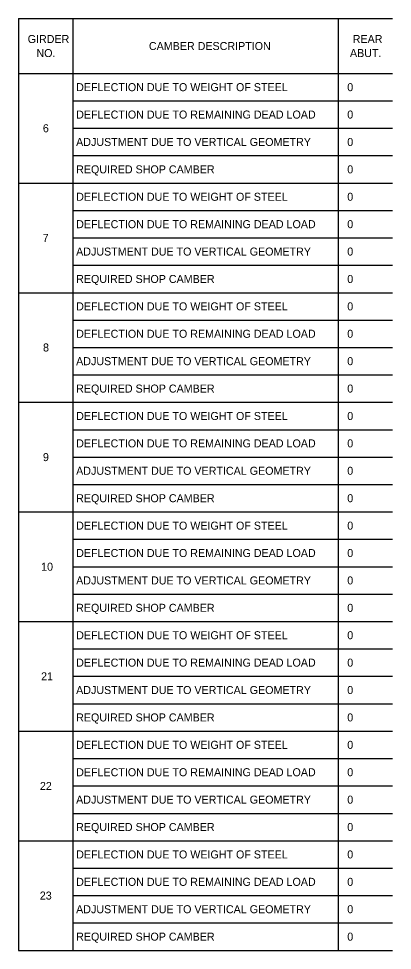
# Model space of a CAD drawing. Extents: x 3 to 33.4, y 1 to 20.5.
# Drawn here: x 3 to 10.19, y 2.58 to 20.5 of the extents above; entities that cross this region are included whole.
import ezdxf

# ---------------------------------------------------------------- set-up
doc = ezdxf.new("R2010")
doc.units = 0
doc.layers.add('BR_X_Beam_Object', color=7, linetype='Continuous')
doc.layers.add('BR_X_Slab_Object', color=7, linetype='Continuous')

msp = doc.modelspace()

# ---------------------------------------------------------------- linework, layer by layer
at = {"layer": 'BR_X_Slab_Object'}
for p, q in [((3, 20.5), (5.319, 20.5)), ((3, 20.5), (3, 2.58)), ((4.041, 20.5), (4.041, 2.58)), ((5.319, 20.5), (10.194, 20.5)), ((9.153, 20.5), (9.153, 2.58)), ((3, 19.446), (5.319, 19.446)), ((5.319, 19.446), (10.194, 19.446)), ((4.041, 18.919), (5.319, 18.919)), ((5.319, 18.919), (10.194, 18.919)), ((4.041, 18.392), (5.319, 18.392)), ((5.319, 18.392), (10.194, 18.392)), ((4.041, 17.865), (5.319, 17.865)), ((5.319, 17.865), (10.194, 17.865)), ((3, 17.338), (5.319, 17.338)), ((5.319, 17.338), (10.194, 17.338)), ((4.041, 16.811), (5.319, 16.811)), ((5.319, 16.811), (10.194, 16.811)), ((4.041, 16.284), (5.319, 16.284)), ((5.319, 16.284), (10.194, 16.284)), ((4.041, 15.756), (5.319, 15.756)), ((5.319, 15.756), (10.194, 15.756)), ((3, 15.229), (5.319, 15.229)), ((5.319, 15.229), (10.194, 15.229)), ((4.041, 14.702), (5.319, 14.702)), ((5.319, 14.702), (10.194, 14.702)), ((4.041, 14.175), (5.319, 14.175)), ((5.319, 14.175), (10.194, 14.175)), ((4.041, 13.648), (5.319, 13.648)), ((5.319, 13.648), (10.194, 13.648)), ((3, 13.121), (5.319, 13.121)), ((5.319, 13.121), (10.194, 13.121)), ((4.041, 12.594), (5.319, 12.594)), ((5.319, 12.594), (10.194, 12.594)), ((4.041, 12.067), (5.319, 12.067)), ((5.319, 12.067), (10.194, 12.067)), ((4.041, 11.54), (5.319, 11.54)), ((5.319, 11.54), (10.194, 11.54)), ((3, 11.013), (5.319, 11.013)), ((5.319, 11.013), (10.194, 11.013)), ((4.041, 10.486), (5.319, 10.486)), ((5.319, 10.486), (10.194, 10.486)), ((4.041, 9.959), (5.319, 9.959)), ((5.319, 9.959), (10.194, 9.959)), ((4.041, 9.432), (5.319, 9.432)), ((5.319, 9.432), (10.194, 9.432)), ((3, 8.905), (5.319, 8.905)), ((5.319, 8.905), (10.194, 8.905)), ((4.041, 8.378), (5.319, 8.378)), ((5.319, 8.378), (10.194, 8.378)), ((4.041, 7.851), (5.319, 7.851)), ((5.319, 7.851), (10.194, 7.851)), ((4.041, 7.324), (5.319, 7.324)), ((5.319, 7.324), (10.194, 7.324)), ((3, 6.796), (5.319, 6.796)), ((5.319, 6.796), (10.194, 6.796)), ((4.041, 6.269), (5.319, 6.269)), ((5.319, 6.269), (10.194, 6.269)), ((4.041, 5.742), (5.319, 5.742)), ((5.319, 5.742), (10.194, 5.742)), ((4.041, 5.215), (5.319, 5.215)), ((5.319, 5.215), (10.194, 5.215)), ((3, 4.688), (5.319, 4.688)), ((5.319, 4.688), (10.194, 4.688)), ((4.041, 4.161), (5.319, 4.161)), ((5.319, 4.161), (10.194, 4.161)), ((4.041, 3.634), (5.319, 3.634)), ((5.319, 3.634), (10.194, 3.634)), ((4.041, 3.107), (5.319, 3.107)), ((5.319, 3.107), (10.194, 3.107)), ((3, 2.58), (5.319, 2.58)), ((5.319, 2.58), (10.194, 2.58))]:
    msp.add_line(p, q, dxfattribs=at)

# ---------------------------------------------------------------- texts
at = {"layer": 'BR_X_Beam_Object'}
for s, p in [('GIRDER', (3.175, 20.031)), ('REAR', (9.431, 20.031)), ('NO.', (3.343, 19.761)), ('CAMBER DESCRIPTION', (5.508, 19.896)), ('ABUT.', (9.378, 19.761)), ('DEFLECTION DUE TO WEIGHT OF STEEL', (4.107, 19.105)), ('0      ', (9.326, 19.105)), ('DEFLECTION DUE TO REMAINING DEAD LOAD', (4.107, 18.578)), ('0      ', (9.326, 18.578)), ('6', (3.467, 18.315)), ('ADJUSTMENT DUE TO VERTICAL GEOMETRY', (4.107, 18.051)), ('0      ', (9.326, 18.051)), ('REQUIRED SHOP CAMBER', (4.107, 17.524)), ('0      ', (9.326, 17.524)), ('DEFLECTION DUE TO WEIGHT OF STEEL', (4.107, 16.997)), ('0      ', (9.326, 16.997)), ('DEFLECTION DUE TO REMAINING DEAD LOAD', (4.107, 16.47)), ('0      ', (9.326, 16.47)), ('7', (3.464, 16.207)), ('ADJUSTMENT DUE TO VERTICAL GEOMETRY', (4.107, 15.943)), ('0      ', (9.326, 15.943)), ('REQUIRED SHOP CAMBER', (4.107, 15.416)), ('0      ', (9.326, 15.416)), ('DEFLECTION DUE TO WEIGHT OF STEEL', (4.107, 14.889)), ('0      ', (9.326, 14.889)), ('DEFLECTION DUE TO REMAINING DEAD LOAD', (4.107, 14.362)), ('0      ', (9.326, 14.362)), ('8', (3.47, 14.098)), ('ADJUSTMENT DUE TO VERTICAL GEOMETRY', (4.107, 13.835)), ('0      ', (9.326, 13.835)), ('REQUIRED SHOP CAMBER', (4.107, 13.308)), ('0      ', (9.326, 13.308)), ('DEFLECTION DUE TO WEIGHT OF STEEL', (4.107, 12.781)), ('0      ', (9.326, 12.781)), ('DEFLECTION DUE TO REMAINING DEAD LOAD', (4.107, 12.254)), ('0      ', (9.326, 12.254)), ('9', (3.468, 11.99)), ('ADJUSTMENT DUE TO VERTICAL GEOMETRY', (4.107, 11.727)), ('0      ', (9.326, 11.727)), ('REQUIRED SHOP CAMBER', (4.107, 11.199)), ('0      ', (9.326, 11.199)), ('DEFLECTION DUE TO WEIGHT OF STEEL', (4.107, 10.672)), ('0      ', (9.326, 10.672)), ('DEFLECTION DUE TO REMAINING DEAD LOAD', (4.107, 10.145)), ('0      ', (9.326, 10.145)), ('10', (3.433, 9.882)), ('ADJUSTMENT DUE TO VERTICAL GEOMETRY', (4.107, 9.618)), ('0      ', (9.326, 9.618)), ('REQUIRED SHOP CAMBER', (4.107, 9.091)), ('0      ', (9.326, 9.091)), ('DEFLECTION DUE TO WEIGHT OF STEEL', (4.107, 8.564)), ('0      ', (9.326, 8.564)), ('DEFLECTION DUE TO REMAINING DEAD LOAD', (4.107, 8.037)), ('0      ', (9.326, 8.037)), ('21', (3.433, 7.774)), ('ADJUSTMENT DUE TO VERTICAL GEOMETRY', (4.107, 7.51)), ('0      ', (9.326, 7.51)), ('REQUIRED SHOP CAMBER', (4.107, 6.983)), ('0      ', (9.326, 6.983)), ('DEFLECTION DUE TO WEIGHT OF STEEL', (4.107, 6.456)), ('0      ', (9.326, 6.456)), ('DEFLECTION DUE TO REMAINING DEAD LOAD', (4.107, 5.929)), ('0      ', (9.326, 5.929)), ('22', (3.41, 5.665)), ('ADJUSTMENT DUE TO VERTICAL GEOMETRY', (4.107, 5.402)), ('0      ', (9.326, 5.402)), ('REQUIRED SHOP CAMBER', (4.107, 4.875)), ('0      ', (9.326, 4.875)), ('DEFLECTION DUE TO WEIGHT OF STEEL', (4.107, 4.348)), ('0      ', (9.326, 4.348)), ('DEFLECTION DUE TO REMAINING DEAD LOAD', (4.107, 3.821)), ('0      ', (9.326, 3.821)), ('23', (3.408, 3.557)), ('ADJUSTMENT DUE TO VERTICAL GEOMETRY', (4.107, 3.294)), ('0      ', (9.326, 3.294)), ('REQUIRED SHOP CAMBER', (4.107, 2.767)), ('0      ', (9.326, 2.767))]:
    msp.add_text(s, height=0.154, dxfattribs=at).set_placement(p)

doc.saveas('drawing.dxf')
